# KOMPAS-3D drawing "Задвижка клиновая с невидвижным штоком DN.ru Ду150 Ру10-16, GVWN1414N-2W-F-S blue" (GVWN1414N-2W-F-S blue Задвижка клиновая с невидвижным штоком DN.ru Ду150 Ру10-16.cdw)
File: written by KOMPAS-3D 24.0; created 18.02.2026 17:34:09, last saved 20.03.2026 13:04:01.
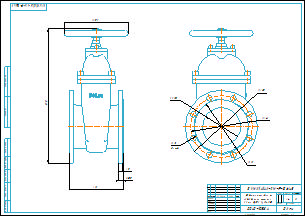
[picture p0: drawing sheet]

Document properties: Автор: R2D2; Форматы листов документа: A2; Полное имя файла: GVWN1414N-2W-F-S blue Задвижка клиновая с невидвижным штоком DN.ru Ду150 Ру10-16.m3d; Масса: 24; Наименование: Задвижка клиновая с невидвижным штоком DN.ru Ду150 Ру10-16; Количество листов документа: 1; Примечание: D040-10584

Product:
- Part/product: Задвижка клиновая с невидвижным штоком DN.ru Ду150 Ру10-16  | designation GVWN1414N-2W-F-S blue
    Масса: 24
    Раздел спецификации: Прочие изделия
    Примечание: D040-10584

Views: Вид 1, Спереди, Проекционный вид 2
Referenced files in E:\Работа\Зайцев\GVWN1414N-2W-F-S blue Задвижка клиновая с невидвижным штоком DN.ru Ду40-300 Ру10-16\DN150\: GVWN1414N-2W-F-S blue Задвижка клиновая с невидвижным штоком DN.ru Ду150 Ру10-16.m3d
Referenced files in E:\Работа\Зайцев\Для компаса\: чертеж DN.ru А3.cdt
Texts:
  GVWN1414N-2W-F-S blue
  чертеж DN.ru А3.cdt
  Задвижка клиновая с
  невидвижным штоком
  DN.ru Ду150 Ру10-16
  Задвижка клиновая с невидвижным штоком DN.ru Ду150 Ру10-16
  GVWN1414N-2W-F-S blue Задвижка клиновая с невидвижным штоком DN.ru Ду150 Ру10-16
Dimensions and other numbers on the sheet: 0; 3; 2; 4; 210; 16,5; 2,5; 525; 250; 285; 240; 150; 23; 8 отв.; 1:2; 1; 24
